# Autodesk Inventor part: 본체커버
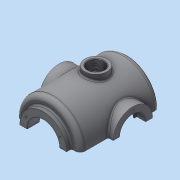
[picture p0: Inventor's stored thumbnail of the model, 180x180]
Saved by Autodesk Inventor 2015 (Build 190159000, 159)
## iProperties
Created: 2016-02
Part Number: 본체커버
Material: 알루미늄 6061
Document SubType Name: Modeling
Designer: mduedu
Density: 2.71 g/cm^3
Mass: 1187.07 g
Surface Area: 904.884 cm^2
Volume: 438.034 cm^3
Appearance: 기본값
Author: mduedu
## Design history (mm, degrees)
sketch "스케치2"
  geometry: L1 (0, 90)-(0, -90); L2 (65, -65.993)-(65, 90); L3 (65, 90)-(0, 90); A1 r 100 centre (0, 10) between (0, -90) and (65, -65.993); 2 further points
  constraints: 6 end point, 2 point on circle, 1 centre point, 1 coincident, 1 horizontal, 1 midpoint, 1 parallel, 1 point on line, 1 vertical
  dimensions: "d3" = 180 distance of L1.start L1.end; "d5" = 130 diameter of L2 L1; "d6" = 100 radius of A1
revolve "회전1" sketch "스케치2" stored, may be unused: angle "d7" = 90 deg
sketch "스케치3"
  geometry: C1 r 47.5 at (0, 0); 1 further point
  constraints: 1 centre point, 1 coincident
  dimensions: "d8" = 95 diameter of C1
extrude "돌출2" join sketch "스케치3" distance "d10" = 10; taper "d11" = 0 deg
sketch "스케치5"
  geometry: L1 (47.5, 100)-(47.5, 90) reference; L2 (47.5, 90)-(65, 90) reference; L3 (65, 90)-(65, -65.993) reference; L4 (-65, -65.993)-(-65, 90) reference; L5 (-65, 90)-(-47.5, 90) reference; L6 (-47.5, 90)-(-47.5, 100) reference; L7 (-47.5, 100)-(47.5, 100) reference; L8 (55, 75)-(55, -61.239); L9 (0, 75)-(55, 75); L10 (0, 75)-(0, -80); A1 r 100 centre (0, 10) between (-65, -65.993) and (0, -90) reference; A2 r 100 centre (0, 10) between (0, -90) and (65, -65.993) reference; A3 r 90 centre (0, 10) between (0, -80) and (55, -61.239); 1 further point
  constraints: 6 end point, 2 point on circle, 1 centre point, 1 parallel, 1 perpendicular, 1 point on line, 1 vertical
  dimensions: "d13" = 10 distance between parallel lines of L3 L8; "d14" = 10 radial gap between concentric circles of A3 A1; "d15" = 15 distance between parallel lines of L9 L2
revolve "회전2" sketch "스케치5" stored, may be unused: angle "d16" = 90 deg
hole "구멍1" diameter "d19" = 65; stored, may be unused: countersink angle "d23" = 90 deg, drill point angle "d25" = 118 deg; dims "d17" = 10, "d18" = 10, "d20" = 6, "d21" = 4, "d22" = 2, "d24" = 8
node "작업 평면1"
sketch "스케치6"
  geometry: L1 (47.5, 100)-(-47.5, 100) reference; C1 r 40 at (0, -7); 1 further point
  constraints: 1 centre point, 1 vertical alignment
  dimensions: "d27" = 80 diameter of C1; "d29" = 107 distance from line of C1.centre L1
extrude "돌출3" join sketch "스케치6" stored distance "d30" = 10; taper "d31" = 0 deg
hole "구멍2" diameter "d34" = 42; stored, may be unused: countersink angle "d38" = 90 deg, drill point angle "d40" = 118 deg; dims "d32" = 10, "d33" = 10, "d35" = 6, "d36" = 52, "d37" = 18, "d39" = 8
sketch "스케치7" dims "d41" = 65
  geometry: C1 r 40 at (0, 0) reference; 3 further points
  constraints: 2 vertical alignment, 1 coincident, 2 other
hole "구멍3" sketch "스케치7" at (0, 32.5) diameter "d43" = 3.242; stored, may be unused: countersink angle "d47" = 90 deg, drill point angle "d49" = 118 deg; dims "d44" = 11, "d45" = 13, "d46" = 18, "d48" = 13
sketch "스케치8" dims "d53" = 80
  geometry: 3 further points
  constraints: 2 vertical alignment, 1 coincident, 2 other
hole "구멍4" sketch "스케치8" at (0, -40) diameter "d56" = 3.242; stored, may be unused: countersink angle "d60" = 90 deg, drill point angle "d62" = 118 deg; dims "d57" = 11, "d58" = 13, "d59" = 18, "d61" = 13
fillet "모깎기1" dims "d66" = 10
fillet "모깎기2" dims "d67" = 3
fillet "모깎기3" dims "d68" = 0.3
chamfer "모따기1" distance "d69" = 1; stored, may be unused: second distance "d70" = 2, angle "d71" = 45 deg
node "작업 평면5"
sketch "스케치10"
  geometry: L1 (-50, 66)-(50, 66); L2 (50, 66)-(50, 50); L3 (50, 50)-(-50, 50); L4 (-50, 50)-(-50, 66); 2 further points
  constraints: 8 end point, 2 horizontal, 2 vertical, 1 midpoint, 1 vertical alignment
  dimensions: "d177" = 50 distance from line of L3 point (0, 0); "d178" = 100 distance of L1.start L1.end; "d179" = 16 distance of L3.end L1.start
extrude "돌출5" join sketch "스케치10" stored distance "d84" = 10; taper "d85" = 0 deg
sketch "스케치21" dims "d180" = 220, "d182" = 130
  geometry: L1 (65, 58)-(-65, 58); L2 (-65, 58)-(-65, -32); L3 (-65, -32)-(65, -32); L4 (65, -32)-(65, 58); L5 (50, 50)-(50, 66) reference; 4 further points
  constraints: 8 end point, 3 horizontal alignment, 3 midpoint, 2 parallel, 1 horizontal, 1 perpendicular, 1 vertical alignment, 4 other
extrude "돌출13" join sketch "스케치21" distance "d183" = 10; taper "d184" = 0 deg
sketch "스케치11"
  geometry: L1 (-65, 80)-(-65, -61.239) reference; L2 (-100, -97)-(-100, -32) reference; L3 (-65, -42.793)-(-100, -63); L4 (-100, -97)-(-110, -97) reference; 1 further point
  constraints: 2 end point, 2 point on line
  dimensions: "d185" = 34 distance from line of L3.end L4; "d186" = 120 deg angle of L2 L3
feature "리브1" sketch "스케치11" dims "d88" = 1, "d89" = 16, "d90" = 0, "d91" = 0, "d92" = 1, "d93" = 1
fillet "모깎기12"
fillet "모깎기13"
fillet "모깎기16" dims "d167" = 3
fillet "모깎기18"
fillet "모깎기17" dims "d168" = 3
fillet "모깎기19" dims "d187" = 3
node "작업 평면6"
sketch "스케치19"
  geometry: L1 (75, -47)-(75, 33) reference; L2 (-75, -47)-(-75, 33) reference; L3 (75, -7)-(-75, -7); C1 r 22.5 at (0, -7); 1 further point
  constraints: 3 midpoint, 2 end point, 1 centre point
  dimensions: "d149" = 45 diameter of C1
extrude "돌출11" join sketch "스케치19" stored distance "d150" = 10; taper "d151" = 0 deg
hole "구멍6" diameter "d154" = 33.376; stored, may be unused: countersink angle "d158" = 90 deg, drill point angle "d160" = 118 deg; dims "d155" = 6, "d156" = 4, "d157" = 2, "d159" = 8, "d190" = 10, "d191" = 10
fillet "모깎기11" dims "d161" = 3
chamfer "모따기3" distance "d164" = 1; stored, may be unused: second distance "d165" = 2, angle "d166" = 45 deg
sketch "스케치22" dims "d189" = 20
  geometry: L1 (-10, -123)-(10, -123); L2 (10, -123)-(10, -103); L3 (10, -103)-(-10, -103); L4 (-10, -103)-(-10, -123); A1 r 65 centre (0, -58) between (-65, -58) and (65, -58) reference; 2 further points
  constraints: 8 end point, 2 parallel, 1 horizontal, 1 horizontal alignment, 1 midpoint, 1 perpendicular, 1 tangent, 1 vertical alignment, 2 other
  dimensions: "d193" = 30 dimension on L1
extrude "돌출14" cut sketch "스케치22" stored distance "d194" = 10; taper "d195" = 0 deg
fillet "모깎기21" dims "d196" = 3
feature "분할1"
node "솔리드2"
pattern_circular "원형 패턴1" dims angle "d51" = 360 deg
mirror "대칭1"
pattern_circular "원형 패턴2" dims angle "d64" = 360 deg
node "절단 모서리 투영1"
other parameters: "d26" = 75, "d136" = 175
